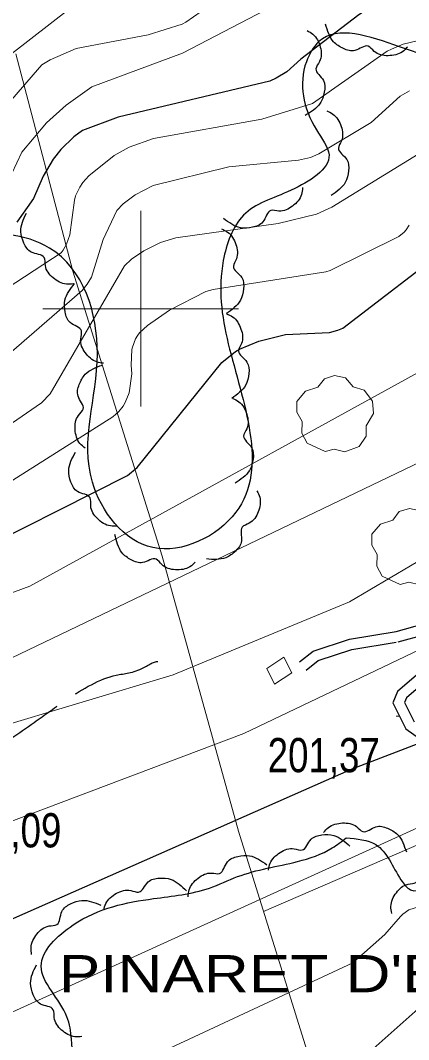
# Model space of a CAD drawing. Extents: x 483847 to 488453, y 4383581 to 4386795.
# Drawn here: x 484969.3 to 485068.4, y 4385313.2 to 4385573.7 of the extents above; entities that cross this region are included whole.
import ezdxf

# ---------------------------------------------------------------- set-up
doc = ezdxf.new("R2010")
doc.units = 0
doc.header["$LTSCALE"] = 3.8
doc.linetypes.add('LONG_DASHED', pattern=[7.5, 6, -1.5])
doc.linetypes.add('MEDIUM_DASHED', pattern=[4.5, 3, -1.5])
for name, color, linetype, lineweight in [('1', 7, 'Continuous', 13), ('27', 7, 'Continuous', 25), ('29', 7, 'Continuous', 13), ('38', 7, 'Continuous', 25), ('47', 7, 'Continuous', 35), ('51', 7, 'Continuous', 13), ('7', 7, 'Continuous', 13), ('8', 7, 'Continuous', 25), ('9', 7, 'Continuous', 13)]:
    doc.layers.add(name, color=color, linetype=linetype, lineweight=lineweight)
doc.layers.add('5', color=7, linetype='Continuous')

msp = doc.modelspace()

# ---------------------------------------------------------------- linework, layer by layer
at = {"layer": '1'}
for p, q in [((485000, 4385525), (485000, 4385475)), ((484975, 4385500), (485025, 4385500))]:
    msp.add_line(p, q, dxfattribs=at)
at = {"layer": '27'}
for points in [[(485103.9, 4385633.91), (485106.01, 4385637.01), (485114.93, 4385644.86), (485126.17, 4385652.73), (485136.38, 4385661.73), (485138.02, 4385665.21), (485141.47, 4385671.83), (485138.88, 4385679.45), (485136.5, 4385686.87), (485135.66, 4385696.31), (485131.76, 4385703.84), (485121.16, 4385713.45), (485113.17, 4385717.29), (485098.54, 4385723.7), (485092.18, 4385725.87), (485073.97, 4385726.91), (485069.66, 4385725.54), (485057.47, 4385722.69), (485041.84, 4385722.5), (485026.03, 4385721.09), (485016.4, 4385718.88), (485006.31, 4385714.3), (485005.29, 4385710.65), (485010.95, 4385708.5), (485020.43, 4385710.34), (485027.55, 4385712.87), (485039.61, 4385714.34), (485055.26, 4385711.35), (485068.84, 4385712.32), (485077.77, 4385709.09), (485079.27, 4385701.34), (485077.25, 4385694.27), (485092.01, 4385685.01), (485096.02, 4385677.26), (485097.6, 4385670.73), (485090.17, 4385658.81), (485076.02, 4385654.39), (485066.78, 4385652.08), (485063.35, 4385642.59), (485065.62, 4385641.62), (485077.4, 4385628.74), (485085.46, 4385615.47), (485095.63, 4385606.6), (485110.56, 4385599.38), (485118, 4385594.73), (485132.59, 4385585.4), (485144.36, 4385578.35), (485155.4, 4385573.52), (485166.19, 4385569.22), (485169.65, 4385564.31), (485163.06, 4385559.29), (485152.18, 4385555.92), (485145.67, 4385554.16), (485137.69, 4385551.04), (485128.05, 4385548.1), (485118.57, 4385544.63), (485110.45, 4385538.77), (485105.67, 4385535.14), (485106.34, 4385526.06), (485119.41, 4385518.5), (485127.51, 4385515.14), (485146.55, 4385512.94), (485160.58, 4385513.64), (485182.93, 4385513.63), (485189.38, 4385511.73), (485180.06, 4385507.11), (485173.34, 4385501.17), (485161.86, 4385497.1), (485148.56, 4385494.29), (485135.74, 4385491.86), (485134.65, 4385491.79)], [(485138.09, 4385491.7), (485117.52, 4385494.92), (485086.01, 4385503.28), (485081.51, 4385513.57), (485077.65, 4385527.72), (485084.73, 4385543.16), (485084.73, 4385555.38), (485066.08, 4385566.96), (485045.5, 4385568.25), (485042.29, 4385563.1), (485044.86, 4385545.73), (485048.08, 4385539.3), (485038.43, 4385530.3), (485026.22, 4385523.86), (485021.07, 4385512.28), (485022.36, 4385491.06), (485024.29, 4385447.96), (485003.07, 4385438.95), (484987.64, 4385455.68), (484988.92, 4385488.48), (484976.71, 4385515.5), (484956.13, 4385517.43), (484943.27, 4385480.76), (484939.42, 4385462.75), (484925.91, 4385453.1), (484916.27, 4385460.18), (484918.84, 4385487.84), (484918.2, 4385505.85), (484902.77, 4385501.35), (484880.26, 4385476.26), (484861.62, 4385445.39), (484883.48, 4385433.16), (484904.7, 4385434.45), (484917.56, 4385425.44), (484886.69, 4385394.57), (484833.97, 4385350.18), (484770.96, 4385312.88), (484729.17, 4385266.56), (484722.1, 4385262.06)], [(485068.1, 4385566.87), (485066.82, 4385565.64), (485063.16, 4385564.65), (485059.63, 4385565.74), (485058.07, 4385567.08), (485054.69, 4385565.98), (485051.75, 4385566.48), (485049.26, 4385568.19), (485047.19, 4385572.7)], [(485042.47, 4385571.08), (485043.98, 4385570.14), (485045.85, 4385566.84), (485045.65, 4385563.15), (485044.74, 4385561.31), (485046.64, 4385558.31), (485046.87, 4385555.33), (485045.83, 4385552.49), (485041.96, 4385549.38)], [(485047.49, 4385550.57), (485049.07, 4385549.75), (485051.18, 4385546.6), (485051.26, 4385542.91), (485050.48, 4385541), (485052.61, 4385538.15), (485053.06, 4385535.2), (485052.23, 4385532.29), (485048.61, 4385528.9)], [(485041.35, 4385530.95), (485041.07, 4385529.2), (485038.74, 4385526.2), (485035.27, 4385524.96), (485033.22, 4385525.09), (485031.18, 4385522.18), (485028.52, 4385520.82), (485025.5, 4385520.69), (485021.14, 4385523.05)], [(484982.78, 4385506.36), (484981.01, 4385506.27), (484977.59, 4385507.91), (484975.64, 4385511.04), (484975.33, 4385513.07), (484972.05, 4385514.45), (484970.16, 4385516.76), (484969.39, 4385519.68), (484970.78, 4385524.44)], [(485020.6, 4385520.39), (485022.18, 4385519.58), (485024.3, 4385516.44), (485024.41, 4385512.75), (485023.65, 4385510.84), (485025.79, 4385508), (485026.26, 4385505.05), (485025.45, 4385502.14), (485021.85, 4385498.73)], [(484990.5, 4385486.06), (484988.75, 4385486.39), (484985.82, 4385488.79), (484984.66, 4385492.3), (484984.85, 4385494.34), (484981.99, 4385496.45), (484980.69, 4385499.14), (484980.64, 4385502.16), (484983.11, 4385506.46)], [(485021.88, 4385498.73), (485023.46, 4385497.93), (485025.6, 4385494.79), (485025.72, 4385491.1), (485024.97, 4385489.19), (485027.12, 4385486.36), (485027.61, 4385483.42), (485026.81, 4385480.5), (485023.22, 4385477.07)], [(484985.8, 4385464.35), (484984.48, 4385465.54), (484983.24, 4385469.12), (484984.09, 4385472.72), (484985.32, 4385474.36), (484983.99, 4385477.66), (484984.29, 4385480.63), (484985.83, 4385483.23), (484990.19, 4385485.6)], [(485023.5, 4385477.08), (485025.05, 4385476.23), (485027.08, 4385473.02), (485027.07, 4385469.33), (485026.25, 4385467.44), (485028.3, 4385464.54), (485028.68, 4385461.58), (485027.78, 4385458.69), (485024.08, 4385455.39)], [(484994.01, 4385444.44), (484992.24, 4385444.47), (484988.94, 4385446.35), (484987.22, 4385449.61), (484987.06, 4385451.66), (484983.88, 4385453.26), (484982.16, 4385455.7), (484981.6, 4385458.67), (484983.32, 4385463.32)], [(485029.68, 4385453.47), (485030.38, 4385451.84), (485030, 4385448.07), (485027.71, 4385445.17), (485025.91, 4385444.19), (485025.73, 4385440.64), (485024.2, 4385438.07), (485021.71, 4385436.35), (485016.76, 4385436.04)], [(485013.91, 4385435.21), (485012.56, 4385434.05), (485008.85, 4385433.28), (485005.4, 4385434.59), (485003.92, 4385436.02), (485000.48, 4385435.12), (484997.58, 4385435.81), (484995.19, 4385437.67), (484993.41, 4385442.3)], [(485052.44, 4385364.8), (485048.92, 4385362.19), (485040.02, 4385358.72), (485024.72, 4385354.86), (485017.53, 4385351.95), (485003.29, 4385349.24), (484982.72, 4385342.51), (484974.56, 4385332.02), (484981.15, 4385319.05), (484982.31, 4385313.35), (484982.65, 4385294.37), (484983.39, 4385269.53), (484987.68, 4385251.41), (484996.81, 4385238.57), (485031.48, 4385237.2), (485037.8, 4385239.34), (485054.61, 4385248.35), (485064.38, 4385252.89), (485078.44, 4385258.07), (485096.56, 4385262.47), (485096.84, 4385262.77), (485103.74, 4385262.86), (485111.59, 4385265.05), (485112.39, 4385270.45), (485114.5, 4385279.23), (485120.51, 4385283.33), (485139.84, 4385291), (485153.97, 4385297.17), (485158.64, 4385300.35), (485154.47, 4385304.25), (485147.71, 4385304.01), (485135.53, 4385313.41), (485131.15, 4385329.54), (485139.45, 4385335.08), (485151.84, 4385327.8), (485165.34, 4385323.12), (485172.43, 4385319.28), (485182.63, 4385318.65), (485183.82, 4385329.99), (485180.64, 4385340.15), (485169.39, 4385361.72), (485166.47, 4385371.34), (485163.13, 4385381.35), (485155.81, 4385395.69), (485151.26, 4385397.82), (485146.5, 4385397.81), (485138.56, 4385396.41), (485131.49, 4385386.65), (485118.99, 4385376.45), (485108.62, 4385373.24), (485099.38, 4385371.24), (485086.02, 4385366.81), (485076.47, 4385354.99), (485068.85, 4385351.52), (485066.46, 4385354.04), (485060, 4385363.04), (485052.44, 4385364.8)], [(485046.7, 4385366.14), (485047.92, 4385367.42), (485051.54, 4385368.57), (485055.11, 4385367.63), (485056.72, 4385366.36), (485060.05, 4385367.61), (485063.01, 4385367.23), (485065.57, 4385365.62), (485067.83, 4385361.21)], [(485032.61, 4385356.54), (485033.05, 4385358.26), (485035.62, 4385361.04), (485039.19, 4385361.98), (485041.22, 4385361.67), (485043.51, 4385364.4), (485046.27, 4385365.52), (485049.29, 4385365.39), (485053.43, 4385362.66)], [(485012.11, 4385349.69), (485012.36, 4385351.45), (485014.64, 4385354.48), (485018.1, 4385355.78), (485020.15, 4385355.68), (485022.14, 4385358.62), (485024.77, 4385360.03), (485027.79, 4385360.2), (485032.19, 4385357.91)], [(485064.1, 4385345.48), (485063.88, 4385347.24), (485065.28, 4385350.76), (485068.28, 4385352.93), (485070.28, 4385353.37), (485071.43, 4385356.74), (485073.6, 4385358.79), (485076.46, 4385359.75), (485081.31, 4385358.7)], [(484990.56, 4385346.28), (484991.09, 4385347.97), (484993.83, 4385350.6), (484997.45, 4385351.33), (484999.46, 4385350.91), (485001.89, 4385353.49), (485004.72, 4385354.46), (485007.73, 4385354.15), (485011.7, 4385351.19)], [(484972.14, 4385334.95), (484971.98, 4385336.72), (484973.5, 4385340.19), (484976.57, 4385342.25), (484978.59, 4385342.62), (484979.85, 4385345.94), (484982.1, 4385347.91), (484984.99, 4385348.78), (484989.8, 4385347.56)], [(484984.94, 4385313.98), (484983.16, 4385313.93), (484979.78, 4385315.65), (484977.91, 4385318.83), (484977.65, 4385320.86), (484974.4, 4385322.31), (484972.56, 4385324.66), (484971.86, 4385327.61), (484973.36, 4385332.33)]]:
    msp.add_spline(points, degree=3, dxfattribs=at)
at = {"layer": '29'}
for points in [[(485047.08, 4385463.52), (485042.54, 4385465.64), (485041.13, 4385468.18), (485041.23, 4385471.16), (485039.86, 4385473.57), (485039.9, 4385476.32), (485042.06, 4385478.92), (485045.25, 4385479.92), (485046.9, 4385482.11), (485049.47, 4385482.94), (485052.33, 4385482.29), (485054.28, 4385480.02), (485057.09, 4385479.2), (485059.22, 4385476.35), (485059.46, 4385473.22), (485057.58, 4385470.07), (485057.58, 4385467.39), (485055.76, 4385464.78), (485052.14, 4385463.44), (485049.37, 4385464.07)], [(485066.21, 4385429.54), (485061.67, 4385431.66), (485060.26, 4385434.2), (485060.36, 4385437.18), (485058.99, 4385439.59), (485059.03, 4385442.34), (485061.19, 4385444.94), (485064.38, 4385445.94), (485066.03, 4385448.13), (485068.6, 4385448.96), (485071.46, 4385448.31), (485073.41, 4385446.04), (485076.22, 4385445.22), (485078.35, 4385442.37), (485078.59, 4385439.24), (485076.71, 4385436.09), (485076.71, 4385433.41), (485074.89, 4385430.8), (485071.27, 4385429.46), (485068.5, 4385430.09)]]:
    msp.add_lwpolyline(points, close=True, dxfattribs=at)
at = {"layer": '38'}
for points in [[(485040.57, 4385409.75), (485044.02, 4385412.48), (485053.29, 4385415.58), (485065.19, 4385417.49), (485072.25, 4385419.43)], [(485074.63, 4385406.38), (485067.86, 4385400.55), (485067.39, 4385399.36), (485069.79, 4385394.43)]]:
    msp.add_lwpolyline(points, dxfattribs=at)
at = {"layer": '38', "linetype": 'MEDIUM_DASHED'}
for points in [[(485042.25, 4385407.62), (485045.33, 4385410.06), (485053.94, 4385412.94), (485065.77, 4385414.84), (485072.62, 4385416.72)], [(485072.8, 4385408.39), (485065.59, 4385402.17), (485064.42, 4385399.25), (485067.66, 4385392.6), (485071.21, 4385390.15)]]:
    msp.add_lwpolyline(points, dxfattribs=at)
at = {"layer": '38', "linetype": 'LONG_DASHED'}
msp.add_spline([(484772.07, 4385119.63), (484769.98, 4385138.08), (484766.98, 4385149.74), (484762.76, 4385158.33), (484754.75, 4385167.27), (484750.43, 4385173.05), (484744.56, 4385184.23), (484744.15, 4385189.24), (484746.62, 4385195.72), (484749.84, 4385199.24), (484755.88, 4385204.8), (484766.45, 4385212.92), (484778.44, 4385220.26), (484781.88, 4385222.98), (484798.93, 4385240.35), (484810.56, 4385251.3), (484818.83, 4385261.04), (484829.7, 4385270.94), (484842.52, 4385281.1), (484851.69, 4385289.41), (484862.06, 4385297.43), (484869.01, 4385304.16), (484877.75, 4385312.52), (484899.5, 4385335.07), (484909.71, 4385345.12), (484916.56, 4385351.21), (484928.9, 4385360.47), (484933.81, 4385364.46), (484946.05, 4385374.77), (484960.9, 4385386.1), (484972.76, 4385394.27), (484981.18, 4385400.17), (484993.7, 4385406.34), (485000.81, 4385408.31), (485004.8, 4385409.49), (485004.99, 4385408.49)], degree=3, dxfattribs=at)
at = {"layer": '47', "lineweight": 13}
msp.add_lwpolyline([(485038.58, 4385406.97), (485034.12, 4385404.02), (485032.21, 4385408.09), (485036.56, 4385410.91)], close=True, dxfattribs=at)
at = {"layer": '51'}
for points in [[(484968.09, 4385565.09), (484982.67, 4385509.56), (485005.49, 4385436.77), (485024.94, 4385366.52), (485046.61, 4385297.12), (485097.73, 4385141.64), (485136.69, 4385144.74), (485137.44, 4385146.34), (485129.42, 4385169.56)], [(485153.65, 4385399.89), (485102.04, 4385376.52), (485031.36, 4385345.95)]]:
    msp.add_lwpolyline(points, dxfattribs=at)
at = {"layer": '7'}
msp.add_line((485065.2, 4385395.91), (485066.2, 4385395.91), dxfattribs=at)
at = {"layer": '8'}
for points in [[(485155.67, 4385572.14), (485105.49, 4385571.16), (485097.11, 4385571.99), (485087.25, 4385574.35), (485076.45, 4385578.57), (485070.88, 4385579.5), (485066.95, 4385579.44), (485062.27, 4385578.39), (485058.2, 4385576.7), (485055.69, 4385575.06), (485040.92, 4385563.73), (485037.31, 4385560.55), (485034.6, 4385558.9), (485032.93, 4385558.16), (484994.23, 4385548.96), (484985.14, 4385545.52), (484982.89, 4385543.88), (484979.63, 4385540.69), (484977.61, 4385538.2), (484975.09, 4385533.87), (484972.61, 4385528.16), (484968.32, 4385522.08)], [(485030.13, 4385491.71), (485036.93, 4385493.4), (485048.23, 4385493.94), (485050.37, 4385494.51), (485051.6, 4385495.02), (485079.76, 4385516.62), (485081.84, 4385517.32), (485082.89, 4385517.48), (485085.95, 4385517.65), (485101.54, 4385515.53), (485117.03, 4385509.3), (485119.93, 4385508.78), (485127.27, 4385508.56), (485140.41, 4385510.34), (485163.12, 4385517.34), (485170.62, 4385521.07), (485172.63, 4385521.74), (485180.96, 4385522.73), (485197.53, 4385526.67), (485277.02, 4385558.31), (485303.08, 4385566.07), (485307.43, 4385568.38), (485314.82, 4385573.25)], [(484953.02, 4385435.42), (484996.6, 4385457.39), (484999.11, 4385459.38), (485020.7, 4385486.27), (485024.23, 4385489.05), (485025.24, 4385489.62), (485030.13, 4385491.71)], [(485261.67, 4385471.15), (485247.08, 4385459.38), (485242.22, 4385456.39), (485200.45, 4385439.21), (485196.72, 4385438.49), (485179.29, 4385438.22), (485154.72, 4385433.77), (485138.23, 4385428.4), (485134.34, 4385426.84), (485129.23, 4385425.36), (485128.13, 4385424.78), (485126.48, 4385423.52), (485125.43, 4385421.58), (485124.9, 4385419.73), (485124.42, 4385419.03), (485123.38, 4385417.93), (485122.22, 4385416.91), (485087.22, 4385395.08), (485053.89, 4385382.33), (484777.81, 4385260.43)]]:
    msp.add_lwpolyline(points, dxfattribs=at)
at = {"layer": '9'}
for points in [[(485267.72, 4385688.81), (485266.84, 4385687.22), (485254.6, 4385673.44), (485238.08, 4385657.98), (485236.05, 4385655.63), (485221.23, 4385643.55), (485212.02, 4385638.61), (485107.11, 4385606.07), (485065.87, 4385611.36), (485037.92, 4385606.95), (485032.6, 4385605.13), (484996.64, 4385588.19), (484906.88, 4385518.52)], [(485180.96, 4385614.14), (485125.15, 4385593.14), (485123.38, 4385592.75), (485121.79, 4385592.58), (485114.22, 4385593.13), (485078.59, 4385600.36), (485072.1, 4385600.97), (485064.86, 4385600.44), (485045.95, 4385595.32), (485031.92, 4385589.2), (485023.32, 4385583.97), (485019.01, 4385579.93), (485015.39, 4385575.91), (485011.49, 4385573.2), (485010.6, 4385572.72), (485001.91, 4385570.02), (484983.51, 4385566.51), (484976.9, 4385563.63), (484974.75, 4385562.33), (484957.08, 4385542.04)], [(485327.24, 4385606.07), (485174.91, 4385544.1), (485124.07, 4385538.3), (485115.85, 4385538.65), (485095.19, 4385542.77), (485077.15, 4385541.67), (485072.99, 4385540.53), (485071.99, 4385540.15), (485048.84, 4385525.92), (485044.86, 4385524.18), (485035.11, 4385521.8), (485008.96, 4385518.13), (485005.01, 4385516.92), (485000.82, 4385514.8), (484997.6, 4385512.64), (484995.86, 4385510.99), (484976.83, 4385478.27), (484974.61, 4385475.98), (484943.56, 4385454.56)], [(485144.5, 4385583.29), (485128, 4385581.67), (485092.46, 4385588.63), (485065.62, 4385588.48), (485054.45, 4385586.66), (485046.52, 4385584.06), (485010.64, 4385565.27), (484987.54, 4385556.7), (484980.93, 4385552.02), (484975.96, 4385547.53), (484969.64, 4385539.96), (484967.11, 4385534.52)], [(485043.86, 4385552.48), (485062.93, 4385565.78), (485064, 4385566.34), (485067.04, 4385567.59), (485074.49, 4385569.39), (485077.21, 4385569.53), (485078.96, 4385569.18), (485090.56, 4385565.76), (485117.98, 4385562.23), (485155.86, 4385562.5)], [(484954.65, 4385478.31), (484985, 4385504.65), (484986.32, 4385506.26), (484987.39, 4385508.09), (484990.37, 4385517.72), (484993.89, 4385525.07), (484995.47, 4385526.8), (484998.61, 4385529.09), (485003.19, 4385531.51), (485022.49, 4385536.24), (485040.32, 4385537.92), (485043.32, 4385538.67), (485045.51, 4385539.56), (485058.85, 4385547.55), (485066.28, 4385554.28), (485068.65, 4385555.68)], [(484895.78, 4385459.43), (484979.64, 4385514.24), (484980.2, 4385514.96), (484981.01, 4385516.47), (484981.86, 4385518.89), (484983.06, 4385527.74), (484983.37, 4385528.81), (484984.41, 4385531.06), (484985.22, 4385532.28), (484986.74, 4385533.97), (484993.17, 4385539.18), (484997.03, 4385541.28), (485003.26, 4385543.5), (485030.95, 4385548.42), (485043.86, 4385552.48)], [(485261.49, 4385537), (485231.97, 4385525.93), (485210.02, 4385511.5), (485208.49, 4385510.69), (485128.08, 4385498.67), (485109.63, 4385500.29), (485105.32, 4385499.99), (485102.84, 4385499.59), (485094.48, 4385496.74), (484971.71, 4385429.08), (484909.59, 4385406.14)], [(484946.15, 4385442.8), (484992.86, 4385472.38), (484994.37, 4385473.7), (484995.48, 4385475.05), (484996.05, 4385476.01), (484997, 4385478.46), (484997.75, 4385483.39), (484997.55, 4385485.6), (484997.68, 4385489.54), (484997.85, 4385490.21), (484998.66, 4385492.27), (484999.23, 4385493.26), (484999.69, 4385493.82), (485001.74, 4385495.7), (485007.34, 4385499.61), (485016.66, 4385504.41), (485018.47, 4385504.9), (485047.3, 4385509.43), (485048.4, 4385509.78), (485065.91, 4385518.41), (485067.3, 4385519.58), (485067.8, 4385520.13), (485068.58, 4385521.31)], [(484674.5, 4385265.7), (484710.01, 4385288.04), (484750.8, 4385303.05), (484860.33, 4385359.54), (485079.99, 4385464.95), (485081.67, 4385466.28), (485089.78, 4385474.12), (485091.78, 4385475.4), (485099.75, 4385479.19), (485102.45, 4385479.84), (485151.07, 4385485.69)], [(484938.49, 4385385.51), (485008.27, 4385406.46), (485053.35, 4385425.05), (485074.05, 4385437.35), (485087.01, 4385447.85), (485096.98, 4385458.74), (485099.16, 4385460.36), (485110.52, 4385465.49), (485113.06, 4385465.99), (485125.73, 4385466.65), (485181.83, 4385474.67)], [(485382.47, 4385473.16), (485349.11, 4385464.77), (485305.06, 4385449), (485265.15, 4385425.62), (485224.59, 4385396.48), (485207.83, 4385390.17), (485068.44, 4385346.38), (485066.97, 4385345.31), (485066.31, 4385344.71), (485062.35, 4385340.08), (485054.14, 4385332.87), (484883.38, 4385253.17)], [(484909.29, 4385347.22), (485026.34, 4385391.41), (485071.27, 4385412.94), (485094.19, 4385422.07), (485106.17, 4385429.64), (485118.51, 4385442.39), (485126.82, 4385446.07), (485158.97, 4385455.98), (485159.1, 4385455.99)], [(484767.17, 4385173.58), (485050.82, 4385305.37), (485057.03, 4385308.78), (485070.82, 4385321.07), (485072.86, 4385322.34), (485078.99, 4385324.87), (485154.91, 4385344.97), (485220.59, 4385375.39), (485225.52, 4385379.41), (485298.21, 4385425.54)], [(485185.51, 4385412.8), (485147.26, 4385406.25), (485143.11, 4385404.99), (485140.9, 4385403.98), (485121.36, 4385390.31), (485097.98, 4385379.73), (484757.4, 4385224.8)]]:
    msp.add_lwpolyline(points, dxfattribs=at)

# ---------------------------------------------------------------- texts
at = {"layer": '5', "width": 1.25}
msp.add_text("PINARET D'EN T¢FOL", height=9.5, dxfattribs=at).set_placement((484979.07, 4385325.31))
at = {"layer": '7', "width": 0.8}
for s, p in [('201,37', (485032.42, 4385381.54)), ('208,09', (484951.1, 4385362.33))]:
    msp.add_text(s, height=8.75, dxfattribs=at).set_placement(p)

doc.saveas('drawing.dxf')
